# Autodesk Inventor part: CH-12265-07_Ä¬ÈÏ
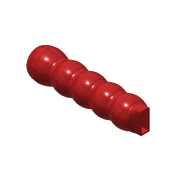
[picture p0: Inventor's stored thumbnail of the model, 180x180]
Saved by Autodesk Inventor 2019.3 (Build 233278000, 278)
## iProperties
Created: 2012-09
Part Number: CH-12265-07_Ä¬ÈÏ
Material: Ogólny
Document SubType Name: Modeling
Designer: CADENGINEERING4
Density: 1 g/cm^3
Appearance: Jasnoczerwona
Author: CADENGINEERING4
Revision Number: ÈÎºÎ
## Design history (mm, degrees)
feature "NONE"
node "Bryła1"
